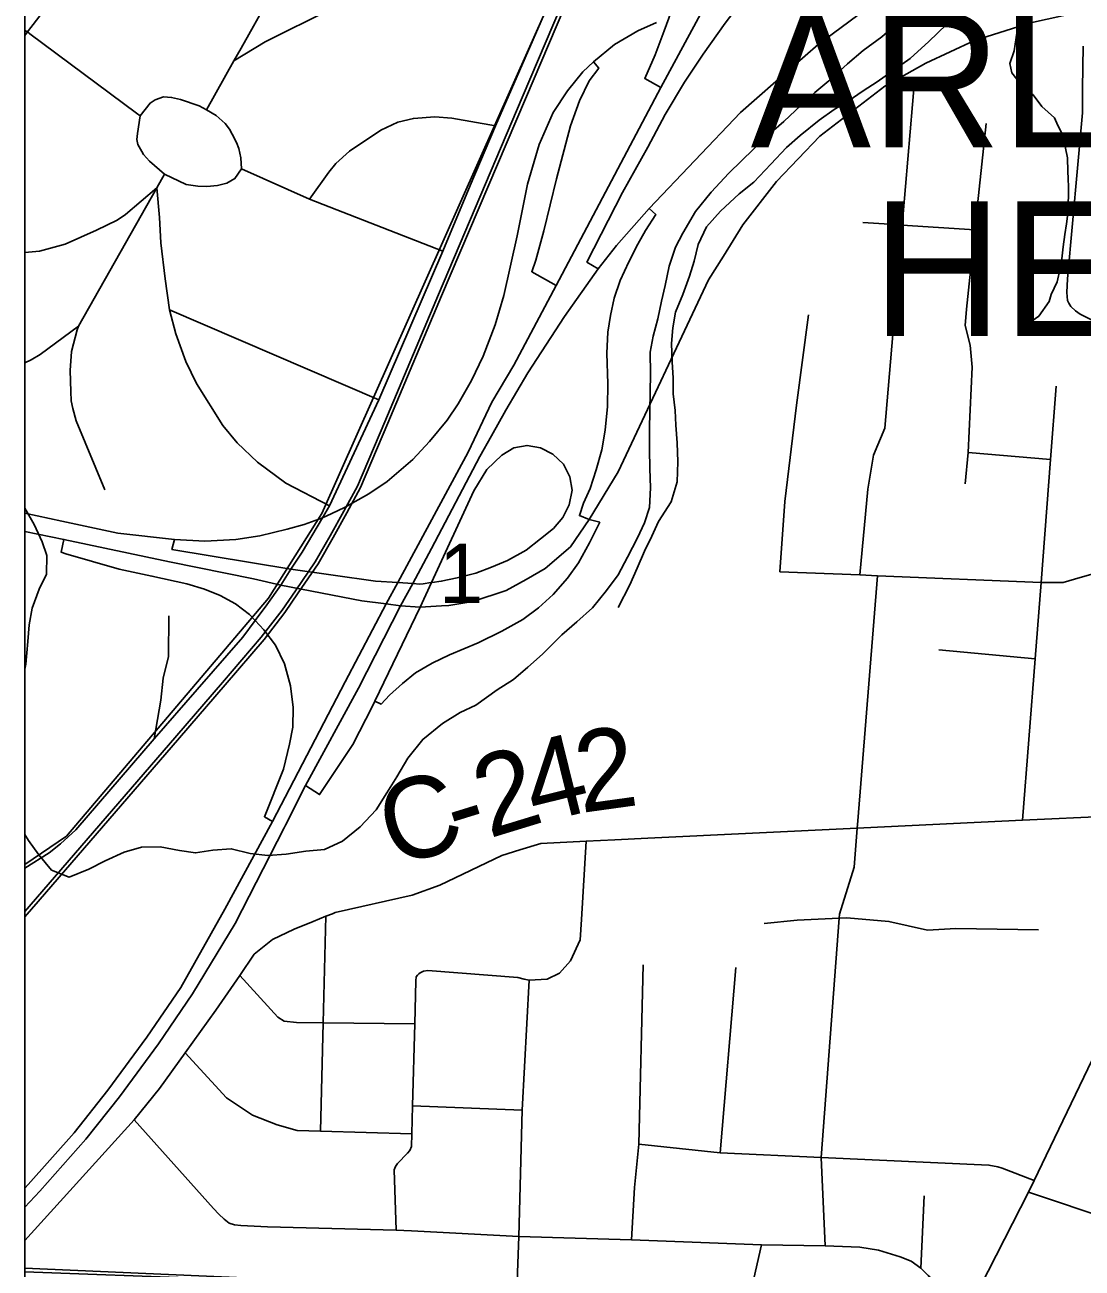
# Model space of a CAD drawing. Extents: x 0 to 34, y -3.9 to 26.2.
# Drawn here: x 2.1 to 2.843, y 17.395 to 18.269 of the extents above; entities that cross this region are included whole.
import ezdxf

# ---------------------------------------------------------------- set-up
doc = ezdxf.new("R2010")
doc.units = 0
for name, color, linetype in [('GM_X_City_Street', 7, 'Continuous'), ('GM_X_Corporation_Text', 7, 'Continuous'), ('GM_X_County_Road', 7, 'Continuous'), ('GM_X_County_Road_Text', 7, 'Continuous'), ('GM_X_Interchange_Ramps', 7, 'Continuous'), ('GM_X_Interstate_Route', 7, 'Continuous'), ('GM_X_Minor_River', 7, 'Continuous'), ('GM_X_Rail_Line', 7, 'Continuous'), ('GM_X_Section_Text', 7, 'Continuous'), ('GM_X_State_Route', 7, 'Continuous'), ('GM_X_State_Shield', 7, 'Continuous'), ('GM_X_Township_Road', 7, 'Continuous'), ('GM_X_US_Route', 7, 'Continuous')]:
    doc.layers.add(name, color=color, linetype=linetype)

msp = doc.modelspace()

# ---------------------------------------------------------------- linework, layer by layer
at = {"layer": 'GM_X_City_Street'}
for p, q in [((2.2017, 18.06834), (2.34872, 18.00506)), ((2.82086, 17.96321), (2.76293, 17.96811)), ((2.81, 17.82289), (2.7424, 17.82925)), ((2.58856, 17.47577), (2.59976, 17.60609)), ((2.72979, 17.39475), (2.73193, 17.44556))]:
    msp.add_line(p, q, dxfattribs=at)
for points in [[(2.252, 18.25229), (2.27147, 18.28708), (2.29313, 18.32578), (2.30483, 18.34095), (2.31486, 18.37267), (2.31716, 18.39339), (2.31863, 18.40046), (2.31847, 18.41032), (2.32044, 18.42331), (2.32978, 18.46946), (2.35869, 18.60321), (2.37338, 18.67118), (2.37626, 18.68188), (2.37967, 18.69168), (2.41636, 18.78764)], [(2.1, 18.26121), (2.10183, 18.26363), (2.20602, 18.39914)], [(2.24694, 18.24325), (2.26896, 18.25672), (2.31499, 18.2797), (2.32792, 18.28561), (2.34829, 18.29193), (2.37801, 18.297), (2.40044, 18.29805), (2.41979, 18.29688), (2.43333, 18.29416), (2.44208, 18.29109), (2.46841, 18.28405)], [(2.1, 18.26465), (2.10183, 18.26363), (2.1036, 18.26232), (2.17843, 18.20647), (2.18093, 18.20462), (2.17907, 18.19215), (2.17871, 18.18801), (2.17943, 18.18442), (2.18229, 18.17954), (2.18342, 18.1776), (2.18763, 18.17283), (2.1982, 18.16361), (2.21339, 18.15639), (2.2215, 18.1553), (2.22779, 18.15512), (2.23534, 18.15566), (2.2419, 18.15731), (2.24766, 18.16061), (2.25235, 18.16735), (2.29994, 18.1462), (2.39377, 18.10962)], [(2.22767, 18.2088), (2.24694, 18.24325), (2.252, 18.25229)], [(2.88928, 18.05596), (2.86008, 18.05748), (2.85627, 18.05868), (2.84953, 18.06118), (2.84165, 18.06538), (2.8383, 18.06755), (2.83515, 18.07076), (2.83363, 18.07289), (2.83279, 18.07492), (2.8323, 18.0804), (2.83279, 18.09011), (2.84328, 18.20683), (2.84342, 18.22389), (2.84367, 18.25354)], [(2.68673, 17.88194), (2.69242, 17.94224), (2.69643, 17.96606), (2.7045, 17.98522), (2.71659, 18.12788), (2.71727, 18.13583), (2.72543, 18.23196)], [(2.18093, 18.20462), (2.188, 18.21366), (2.19148, 18.21588), (2.19754, 18.21793), (2.20316, 18.21768), (2.20927, 18.21616), (2.22248, 18.2117), (2.22767, 18.2088), (2.23449, 18.20499), (2.24073, 18.19934), (2.2438, 18.19528), (2.24565, 18.19187), (2.24882, 18.18604), (2.25026, 18.18173), (2.25188, 18.17526), (2.25235, 18.16735)], [(2.29994, 18.1462), (2.31355, 18.16517), (2.31853, 18.17114), (2.32818, 18.17982), (2.35013, 18.19457), (2.36201, 18.20034), (2.37308, 18.20283), (2.38822, 18.20399), (2.40017, 18.20299), (2.43076, 18.19774)], [(2.76096, 17.946), (2.76293, 17.96811), (2.76588, 18.02792), (2.76434, 18.04354), (2.76086, 18.0573), (2.76188, 18.06867), (2.76771, 18.12455), (2.77552, 18.19938)], [(2.15629, 17.94168), (2.13599, 17.99037), (2.13365, 17.999), (2.13264, 18.00439), (2.13223, 18.01099), (2.13194, 18.02569), (2.13279, 18.0391), (2.13664, 18.05431), (2.13759, 18.05677), (2.19277, 18.15405), (2.1982, 18.16361)], [(2.1, 18.10851), (2.11028, 18.10952), (2.12823, 18.11447), (2.15045, 18.12426), (2.16488, 18.13146), (2.17081, 18.13524), (2.19277, 18.15405)], [(2.3142, 17.93058), (2.28347, 17.94659), (2.26348, 17.96123), (2.2492, 17.97479), (2.2392, 17.98693), (2.22063, 18.01657), (2.21313, 18.03192), (2.20599, 18.05156), (2.2017, 18.06834), (2.19849, 18.09012), (2.19563, 18.11547), (2.19457, 18.13332), (2.19277, 18.15405)], [(2.68891, 18.12969), (2.71143, 18.12822), (2.71659, 18.12788), (2.76771, 18.12455)], [(2.63061, 17.88423), (2.6341, 17.93351), (2.64224, 18.00129), (2.65065, 18.06489)], [(2.1, 18.03112), (2.10453, 18.03306), (2.11072, 18.03691), (2.13759, 18.05677)], [(2.80123, 17.70948), (2.81, 17.82289), (2.81416, 17.87676), (2.82086, 17.96321), (2.82484, 18.01473)], [(2.63061, 17.88423), (2.68673, 17.88194), (2.69927, 17.88143), (2.81416, 17.87676), (2.81497, 17.87672), (2.82977, 17.87671), (2.84163, 17.8802), (2.87483, 17.88958), (2.88714, 17.89306), (2.90505, 17.89563), (2.91019, 17.89573), (2.9134, 17.89579), (2.92783, 17.89464), (2.99185, 17.88955)], [(2.66239, 17.41038), (2.65974, 17.47251), (2.67229, 17.64076), (2.67249, 17.64345), (2.6828, 17.67661), (2.685, 17.704), (2.68541, 17.70905), (2.69927, 17.88143)], [(2.19089, 17.76667), (2.1955, 17.79396), (2.19714, 17.80941), (2.20083, 17.82453), (2.20126, 17.85326)], [(2.61954, 17.63686), (2.64277, 17.63929), (2.67229, 17.64076), (2.67774, 17.64103), (2.70729, 17.63836), (2.73449, 17.63232), (2.75426, 17.63333), (2.81234, 17.63256)], [(2.52626, 17.41465), (2.5284, 17.45147), (2.53152, 17.48173), (2.53453, 17.60796)], [(2.53152, 17.48173), (2.58856, 17.47577), (2.65974, 17.47251), (2.77748, 17.46712), (2.78392, 17.46582), (2.78676, 17.46497), (2.8093, 17.45633)], [(2.80534, 17.44819), (2.86496, 17.42812), (2.89131, 17.41925)], [(2.51758, 17.12749), (2.54316, 17.18144), (2.55677, 17.21015), (2.56874, 17.23538), (2.59596, 17.29282), (2.60561, 17.31317), (2.60637, 17.31502), (2.60713, 17.31721), (2.60763, 17.32003), (2.60818, 17.32952), (2.60851, 17.34852), (2.60891, 17.37183), (2.61767, 17.41103)]]:
    msp.add_lwpolyline(points, dxfattribs=at)
at = {"layer": 'GM_X_County_Road'}
for p, q in [((2.1, 17.4141), (2.17691, 17.49899)), ((2.37166, 17.42083), (2.44718, 17.41695))]:
    msp.add_line(p, q, dxfattribs=at)
for points in [[(2.46841, 18.28405), (2.43076, 18.19774), (2.413, 18.15565), (2.39377, 18.10962), (2.34872, 18.00506), (2.3142, 17.93058), (2.30924, 17.9222), (2.2948, 17.89803), (2.28691, 17.88603), (2.27978, 17.87476), (2.27005, 17.86104), (2.26184, 17.85), (2.25316, 17.83831), (2.22115, 17.80152), (2.19089, 17.76667), (2.13588, 17.70276), (2.12497, 17.69285), (2.11707, 17.68661), (2.1, 17.67582)], [(2.51466, 17.69577), (2.53775, 17.69699), (2.685, 17.704), (2.68969, 17.70429), (2.80123, 17.70948), (2.86287, 17.71234), (2.89258, 17.71372), (2.9002, 17.71408), (2.91352, 17.71571), (2.93964, 17.71941)], [(2.30269, 17.63842), (2.31161, 17.64201), (2.31615, 17.64385), (2.31801, 17.64459), (2.37215, 17.65679), (2.39165, 17.66399), (2.43533, 17.68476), (2.44794, 17.68868), (2.46252, 17.6932), (2.49458, 17.69471), (2.51466, 17.69577)], [(2.44718, 17.41695), (2.44939, 17.50563), (2.45444, 17.59702), (2.46706, 17.59777), (2.47564, 17.60207), (2.48347, 17.61065), (2.49029, 17.62554), (2.49129, 17.63968), (2.49458, 17.69471)], [(2.17691, 17.49899), (2.19454, 17.52099), (2.21258, 17.54595), (2.23431, 17.57602), (2.25105, 17.60046), (2.26126, 17.61536), (2.27399, 17.62574), (2.28931, 17.63302), (2.30269, 17.63842)], [(2.17691, 17.49899), (2.23247, 17.43652), (2.23625, 17.43257), (2.24004, 17.42912), (2.24365, 17.4264), (2.24743, 17.42513), (2.25187, 17.42468), (2.27045, 17.42369), (2.36087, 17.42139), (2.37166, 17.42083)], [(2.43392, 17.1213), (2.43403, 17.125), (2.43418, 17.13007), (2.43582, 17.18633), (2.4374, 17.24037), (2.44181, 17.29534), (2.44535, 17.35214), (2.44587, 17.37897), (2.44718, 17.41695)], [(2.44718, 17.41695), (2.52626, 17.41465), (2.61767, 17.41103), (2.66239, 17.41038)], [(2.66239, 17.41038), (2.68688, 17.40939), (2.70004, 17.40741), (2.70902, 17.40458), (2.71525, 17.40261), (2.72293, 17.39954), (2.72979, 17.39475), (2.73489, 17.38949), (2.73617, 17.38837)]]:
    msp.add_lwpolyline(points, dxfattribs=at)
at = {"layer": 'GM_X_Interchange_Ramps'}
for points in [[(2.1, 18.79438), (2.1, 15.04777)], [(2.56921, 18.35281), (2.56969, 18.35018), (2.57066, 18.34406), (2.55616, 18.28367), (2.55249, 18.27332), (2.54932, 18.26441), (2.54308, 18.24757), (2.53562, 18.23089), (2.54705, 18.22455)], [(2.50293, 18.09716), (2.49501, 18.10186), (2.52013, 18.15089), (2.53773, 18.18255), (2.55012, 18.20558), (2.5635, 18.22828), (2.57677, 18.24802), (2.59212, 18.26974), (2.60135, 18.28166), (2.64575, 18.33806), (2.65448, 18.34905)], [(2.4996, 18.24259), (2.50331, 18.23816), (2.49662, 18.22936), (2.4897, 18.2153), (2.48338, 18.19765), (2.47368, 18.16039), (2.46471, 18.12381), (2.459, 18.10328), (2.45625, 18.09508), (2.47336, 18.0855)], [(2.53872, 18.1395), (2.54339, 18.13543), (2.53609, 18.12409), (2.53075, 18.11436), (2.52439, 18.10195), (2.51845, 18.08897), (2.51422, 18.07655), (2.51154, 18.06439), (2.50972, 18.0525), (2.50902, 18.0379), (2.50965, 18.01622), (2.50936, 18.00034), (2.50792, 17.98363), (2.50551, 17.96991), (2.50155, 17.95592), (2.4973, 17.94278), (2.49267, 17.93234), (2.4897, 17.92372), (2.4965, 17.92091)], [(2.34602, 17.79325), (2.37783, 17.8594), (2.38579, 17.87661), (2.41562, 17.94103), (2.42469, 17.95603), (2.43516, 17.96609), (2.44357, 17.97139), (2.45295, 17.97299), (2.46243, 17.97134), (2.47117, 17.96686), (2.47862, 17.95984), (2.48292, 17.95086), (2.48453, 17.9415), (2.48245, 17.93117), (2.47797, 17.92243), (2.47151, 17.9147), (2.46236, 17.90728), (2.45222, 17.89931), (2.43925, 17.89207), (2.42801, 17.8875), (2.4169, 17.88322), (2.40383, 17.87995), (2.39261, 17.87751), (2.3862, 17.87666)], [(2.34602, 17.79325), (2.35052, 17.79124), (2.35624, 17.79753), (2.36539, 17.80565), (2.37454, 17.81307), (2.38623, 17.8199), (2.39848, 17.82572), (2.41855, 17.8343), (2.43522, 17.8425), (2.45004, 17.85057), (2.46103, 17.85882), (2.47119, 17.86821), (2.48137, 17.87973), (2.48899, 17.89043), (2.49692, 17.90452), (2.50407, 17.91904), (2.4965, 17.92091)], [(2.12749, 17.9069), (2.12557, 17.89786), (2.12889, 17.89685), (2.16628, 17.88599), (2.18928, 17.88116), (2.21387, 17.87579), (2.22632, 17.87188), (2.2372, 17.86762), (2.24808, 17.86161), (2.25788, 17.85419), (2.26184, 17.85), (2.26804, 17.84344), (2.27608, 17.83251), (2.28253, 17.81949), (2.28668, 17.80401), (2.28855, 17.78872), (2.28832, 17.77501), (2.28598, 17.7629), (2.28186, 17.74541), (2.26836, 17.71198), (2.27412, 17.70876)], [(2.38541, 17.87656), (2.37983, 17.87582), (2.3777, 17.87554), (2.37275, 17.87587), (2.36215, 17.87658), (2.34632, 17.87763), (2.28691, 17.88603), (2.20329, 17.89982), (2.20514, 17.90679)], [(2.29727, 17.73387), (2.30711, 17.72757), (2.33039, 17.76269), (2.34437, 17.78983), (2.34602, 17.79325)]]:
    msp.add_lwpolyline(points, dxfattribs=at)
at = {"layer": 'GM_X_Interstate_Route'}
msp.add_line((2.28325, 17.70602), (2.29727, 17.73387), dxfattribs=at)
for points in [[(2.1, 20.9), (2.1, 17.39463), (2.44563, 17.3795), (2.60868, 17.37236), (2.76552, 17.37098), (2.79269, 17.36865), (2.8236, 17.3675), (2.85845, 17.36602), (2.86472, 17.42865), (2.88518, 17.60931), (2.89235, 17.71425), (2.90996, 17.89625), (2.94861, 18.2958)], [(2.27412, 17.70876), (2.32508, 17.8068), (2.35384, 17.86164), (2.36215, 17.87658), (2.41149, 17.96823), (2.42829, 18.00342), (2.44364, 18.02952), (2.47336, 18.0855), (2.54705, 18.22455), (2.57639, 18.27914), (2.60265, 18.33038), (2.61658, 18.3624), (2.62359, 18.38126), (2.62875, 18.3964), (2.63533, 18.41701), (2.6429, 18.44619), (2.65167, 18.49137)], [(2.63934, 18.2388), (2.65749, 18.25472), (2.70163, 18.28758), (2.75337, 18.32061), (2.80689, 18.3504), (2.84268, 18.36874)], [(2.42798, 17.97979), (2.43804, 17.99785), (2.45339, 18.02395), (2.47927, 18.06365), (2.50293, 18.09716), (2.51578, 18.11343), (2.53872, 18.1395), (2.60304, 18.20697), (2.63934, 18.2388)], [(2.3858, 17.90063), (2.41983, 17.96517), (2.42798, 17.97979)], [(2.29727, 17.73387), (2.33451, 17.80243), (2.3639, 17.86033), (2.37275, 17.87587), (2.3858, 17.90063)], [(2.1, 17.45093), (2.10238, 17.45346), (2.13463, 17.48987), (2.15831, 17.51969), (2.18573, 17.55698), (2.20964, 17.59207), (2.24064, 17.64691), (2.27412, 17.70876)], [(2.1, 17.43764), (2.11058, 17.44887), (2.14282, 17.48528), (2.16651, 17.51511), (2.19392, 17.55239), (2.21783, 17.58748), (2.24788, 17.63683), (2.28231, 17.70417), (2.28325, 17.70602)]]:
    msp.add_lwpolyline(points, dxfattribs=at)
at = {"layer": 'GM_X_Minor_River'}
for points in [[(2.71544, 18.27167), (2.70232, 18.26013), (2.68924, 18.2505), (2.67806, 18.2412), (2.66494, 18.22929), (2.6553, 18.22111), (2.64565, 18.21217), (2.63329, 18.20062), (2.62094, 18.18982), (2.59467, 18.16447), (2.58227, 18.15103), (2.5714, 18.13755), (2.56238, 18.12213), (2.55726, 18.11235), (2.55284, 18.09912), (2.54993, 18.0855), (2.54745, 18.07452), (2.54494, 18.06202), (2.54168, 18.04992), (2.53957, 18.03856), (2.53966, 18.02335), (2.53893, 17.98421), (2.53904, 17.97014), (2.53918, 17.95684), (2.53968, 17.94314), (2.53904, 17.92947), (2.53542, 17.91852), (2.53067, 17.90796), (2.52359, 17.89441), (2.51691, 17.882), (2.50873, 17.87113), (2.49902, 17.85877), (2.48783, 17.8491), (2.47742, 17.83979), (2.46388, 17.82636), (2.45346, 17.81706), (2.44344, 17.80851), (2.43192, 17.80112), (2.41692, 17.79039), (2.40582, 17.78527), (2.39353, 17.77753), (2.37966, 17.76639), (2.36918, 17.75328), (2.36134, 17.74013), (2.3543, 17.72886), (2.34687, 17.71683), (2.33564, 17.70488), (2.32331, 17.69486), (2.31068, 17.68901), (2.29738, 17.68775), (2.28368, 17.68572), (2.27076, 17.68483), (2.25826, 17.68621), (2.24504, 17.6895), (2.23213, 17.6886), (2.21995, 17.68655), (2.2086, 17.68829), (2.19498, 17.69083), (2.18208, 17.69069), (2.16987, 17.68712), (2.15647, 17.68092), (2.14498, 17.67505), (2.13122, 17.66961), (2.11879, 17.67441), (2.10988, 17.68522), (2.10248, 17.69524), (2.1, 17.69944)], [(2.51686, 17.85919), (2.52512, 17.875), (2.53027, 17.88668), (2.53543, 17.89875), (2.54056, 17.9093), (2.54531, 17.91947), (2.55429, 17.93336), (2.55835, 17.94735), (2.55899, 17.9614), (2.55848, 17.97472), (2.55758, 17.98728), (2.55701, 17.99755), (2.55572, 18.00936), (2.55554, 18.02039), (2.555, 18.0318), (2.55448, 18.04474), (2.55545, 18.05574), (2.55717, 18.06673), (2.56233, 18.07918), (2.56713, 18.09201), (2.57036, 18.10259), (2.57324, 18.11432), (2.57916, 18.12675), (2.58885, 18.1376), (2.60198, 18.14989), (2.61238, 18.15806), (2.62438, 18.17075), (2.63522, 18.18233), (2.64487, 18.19089), (2.65835, 18.20166), (2.66873, 18.20907), (2.67871, 18.21496), (2.68909, 18.22237), (2.69908, 18.22864), (2.72215, 18.24493), (2.73527, 18.25684), (2.74764, 18.26878)], [(2.79768, 18.27088), (2.79742, 18.26443), (2.79535, 18.25045), (2.79234, 18.24146), (2.7936, 18.23494), (2.80229, 18.22394), (2.80857, 18.2195), (2.81471, 18.21126), (2.82352, 18.20329), (2.82596, 18.19787), (2.82879, 18.19243), (2.8301, 18.18706), (2.83142, 18.18206), (2.83267, 18.17517), (2.83306, 18.16565), (2.83324, 18.1607), (2.83338, 18.15461), (2.83355, 18.14929), (2.83303, 18.13601), (2.83199, 18.12883), (2.83093, 18.12127), (2.82983, 18.11257), (2.82865, 18.10198), (2.82771, 18.09746), (2.82544, 18.08805), (2.82129, 18.0791), (2.81995, 18.07421), (2.81271, 18.06387), (2.80802, 18.06065), (2.81318, 18.05663), (2.81957, 18.05485), (2.8283, 18.05449), (2.83362, 18.05464), (2.84574, 18.05338)], [(2.1, 17.92898), (2.10664, 17.91753), (2.1121, 17.90526), (2.11534, 17.89569), (2.11509, 17.88239), (2.10996, 17.87185), (2.10516, 17.85864), (2.10304, 17.84689), (2.10206, 17.83513), (2.10062, 17.81919), (2.1, 17.81566)]]:
    msp.add_lwpolyline(points, dxfattribs=at)
at = {"layer": 'GM_X_Rail_Line'}
for points in [[(2.1, 17.67839), (2.12929, 17.69843), (2.27121, 17.86552), (2.30871, 17.92525), (2.50353, 18.36306), (2.52175, 18.40822), (2.61624, 18.79403), (2.64614, 18.95801), (2.66015, 19.07324)], [(2.1, 17.64534), (2.10749, 17.65399), (2.20681, 17.76917), (2.23892, 17.80629), (2.26616, 17.83814), (2.28073, 17.8571), (2.29012, 17.87069), (2.30411, 17.89107), (2.31448, 17.90942), (2.32411, 17.92686), (2.33368, 17.94441), (2.35289, 17.98964), (2.39062, 18.07914), (2.44961, 18.2176), (2.48253, 18.29547)], [(2.1, 17.64155), (2.10937, 17.65236), (2.2087, 17.76755), (2.2408, 17.80467), (2.26809, 17.83657), (2.28274, 17.85564), (2.29217, 17.86928), (2.30622, 17.88975), (2.31665, 17.90821), (2.32628, 17.92567), (2.33592, 17.94333), (2.35518, 17.98868), (2.3929, 18.07817), (2.4519, 18.21663), (2.48481, 18.29449)]]:
    msp.add_lwpolyline(points, dxfattribs=at)
at = {"layer": 'GM_X_State_Route'}
for points in [[(2.39288, 17.86026), (2.3979, 17.86055), (2.41483, 17.8633), (2.43826, 17.87108), (2.45229, 17.87875), (2.46567, 17.88643), (2.48344, 17.90178), (2.4965, 17.92091), (2.51702, 17.95445), (2.58055, 18.08939), (2.59094, 18.10609), (2.60461, 18.12806), (2.62829, 18.15844), (2.65867, 18.1904), (2.70444, 18.22552), (2.73317, 18.24166), (2.76749, 18.25753), (2.80676, 18.27008), (2.85161, 18.27982), (2.90688, 18.28838), (2.94884, 18.29528), (2.95371, 18.29598)], [(2.20514, 17.90679), (2.22654, 17.90574), (2.24836, 17.90694), (2.26525, 17.90947), (2.28445, 17.91425), (2.29628, 17.91736), (2.30924, 17.9222), (2.31569, 17.92504), (2.32469, 17.92932), (2.34168, 17.93908), (2.35452, 17.94763), (2.37272, 17.96309), (2.38434, 17.9757), (2.39685, 17.99084), (2.40463, 18.00224), (2.41384, 18.01858), (2.42218, 18.0358), (2.43062, 18.05784), (2.43665, 18.07835), (2.44598, 18.12035), (2.45332, 18.15665), (2.46155, 18.1845), (2.47131, 18.20699), (2.48129, 18.22234), (2.49225, 18.23561), (2.4996, 18.24259), (2.5143, 18.25491), (2.53082, 18.2645), (2.54402, 18.27037)], [(2.1, 17.92532), (2.12608, 17.91974), (2.16534, 17.91144), (2.20514, 17.90679)], [(2.1, 17.91247), (2.12749, 17.9069), (2.20174, 17.89117), (2.26074, 17.87911), (2.27978, 17.87476), (2.33693, 17.86384), (2.35384, 17.86164), (2.3639, 17.86033), (2.37783, 17.8594), (2.39288, 17.86026)]]:
    msp.add_lwpolyline(points, dxfattribs=at)
at = {"layer": 'GM_X_State_Shield'}
msp.add_lwpolyline([(2.1, 18.41824), (2.1, 17.392), (2.86031, 17.36388), (2.95688, 18.38489)], close=True, dxfattribs=at)
at = {"layer": 'GM_X_Township_Road'}
for p, q in [((2.3719, 17.48899), (2.37243, 17.50873)), ((2.37243, 17.50873), (2.44939, 17.50563))]:
    msp.add_line(p, q, dxfattribs=at)
for points in [[(2.31161, 17.64201), (2.30967, 17.56717), (2.30771, 17.49094)], [(2.37243, 17.50873), (2.374, 17.56641), (2.37482, 17.59676), (2.3751, 17.59943), (2.37584, 17.60071), (2.37679, 17.60165), (2.37773, 17.6023), (2.38023, 17.60334), (2.38315, 17.60383), (2.44646, 17.59909), (2.45083, 17.59777), (2.45444, 17.59702)], [(2.25105, 17.60046), (2.27775, 17.57108), (2.28225, 17.56833), (2.29096, 17.56738), (2.30967, 17.56717), (2.374, 17.56641)], [(2.21258, 17.54595), (2.24173, 17.51449), (2.26009, 17.50233), (2.27742, 17.49552), (2.29139, 17.49143), (2.30771, 17.49094), (2.3719, 17.48899)], [(2.36087, 17.42139), (2.35958, 17.46381), (2.36043, 17.46617), (2.36194, 17.46832), (2.36891, 17.4754), (2.37066, 17.47743), (2.37166, 17.48027), (2.3719, 17.48899)]]:
    msp.add_lwpolyline(points, dxfattribs=at)
at = {"layer": 'GM_X_US_Route'}
msp.add_lwpolyline([(2.65123, 17.12275), (2.6901, 17.20311), (2.73245, 17.29071), (2.74698, 17.32399), (2.76575, 17.37045), (2.80534, 17.44819), (2.8093, 17.45633), (2.81495, 17.46795), (2.85873, 17.55917), (2.88541, 17.60878), (2.89864, 17.63338), (2.93964, 17.71941), (2.95645, 17.75236), (2.97303, 17.77663), (3.04543, 17.86568)], dxfattribs=at)

# ---------------------------------------------------------------- texts
at = {"layer": 'GM_X_Corporation_Text'}
for s, p in [('ARLINGTON', (2.61017, 18.18264)), ('HEIGHTS', (2.69559, 18.04995))]:
    msp.add_text(s, height=0.094697, rotation=0.00001, dxfattribs=at).set_placement(p)
at = {"layer": 'GM_X_County_Road_Text'}
for s, rotation, p in [('4', 13.86947, (2.45858, 17.70655)), ('2', 7.91103, (2.49076, 17.71458)), ('2', 16.98568, (2.42616, 17.69663)), ('C', 16.50575, (2.359, 17.67643)), ('-', 17.19532, (2.40412, 17.68981))]:
    msp.add_text(s, height=0.05682, rotation=rotation, dxfattribs=at).set_placement(p)
at = {"layer": 'GM_X_Section_Text'}
msp.add_text('1', height=0.04186, rotation=0.00001, dxfattribs=at).set_placement((2.39102, 17.86217))

doc.saveas('drawing.dxf')
